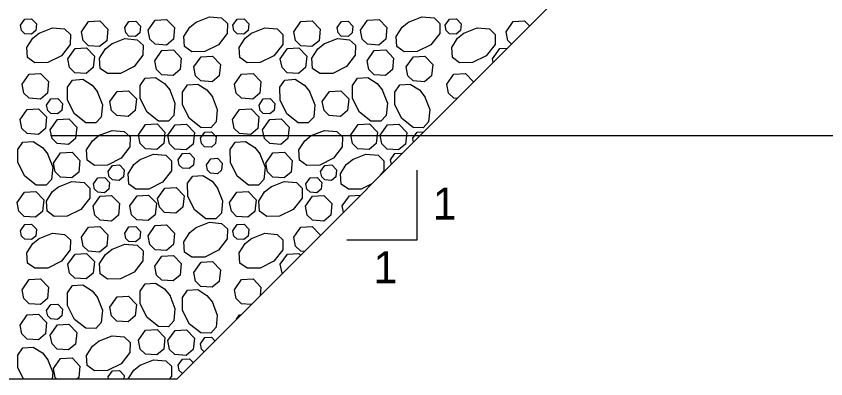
# Model space of a CAD drawing. Extents: x 638079 to 640019, y 297691 to 298879.
# Drawn here: x 639799.9 to 639876.1, y 298707.6 to 298741.7 of the extents above; entities that cross this region are included whole.
import ezdxf

# ---------------------------------------------------------------- set-up
doc = ezdxf.new("R2010")
doc.units = 0
doc.layers.add('1', color=7, linetype='Continuous')

msp = doc.modelspace()

# ---------------------------------------------------------------- linework, layer by layer
at = {"layer": '1'}
for p, q in [((639815.046, 298707.596), (639865.844, 298758.394)), ((639803.122, 298730.456), (639896.763, 298730.456)), ((639837.618, 298727.207), (639837.618, 298720.622)), ((639837.618, 298720.622), (639831.033, 298720.622)), ((639632.166, 298707.596), (639815.046, 298707.596))]:
    msp.add_line(p, q, dxfattribs=at)
for points in [[(639800.314, 298740.827), (639800.717, 298741.401), (639801.361, 298741.438), (639801.809, 298740.974), (639801.744, 298740.323), (639801.346, 298739.992), (639800.71, 298740.038), (639800.411, 298740.329), (639800.314, 298740.827)], [(639812.321, 298740.359), (639812.993, 298741.315), (639814.067, 298741.376), (639814.813, 298740.603), (639814.705, 298739.519), (639814.042, 298738.967), (639812.982, 298739.044), (639812.483, 298739.527), (639812.322, 298740.359)], [(639816.832, 298741.123), (639818.09, 298741.622), (639819.245, 298741.522), (639819.794, 298741), (639819.777, 298740.063), (639818.944, 298738.997), (639817.656, 298738.353), (639816.442, 298738.332), (639815.759, 298738.818), (639815.694, 298739.784), (639816.248, 298740.649), (639816.883, 298741.156)], [(639820.302, 298740.827), (639820.706, 298741.401), (639821.35, 298741.438), (639821.797, 298740.974), (639821.733, 298740.323), (639821.335, 298739.992), (639820.699, 298740.038), (639820.4, 298740.329), (639820.303, 298740.827)], [(639832.31, 298740.359), (639832.982, 298741.315), (639834.055, 298741.376), (639834.801, 298740.603), (639834.693, 298739.519), (639834.03, 298738.967), (639832.971, 298739.044), (639832.472, 298739.527), (639832.31, 298740.359)], [(639836.821, 298741.123), (639838.079, 298741.622), (639839.234, 298741.522), (639839.783, 298741), (639839.766, 298740.063), (639838.932, 298738.997), (639837.644, 298738.353), (639836.43, 298738.332), (639835.747, 298738.818), (639835.682, 298739.784), (639836.237, 298740.649), (639836.872, 298741.156)], [(639840.291, 298740.827), (639840.694, 298741.401), (639841.338, 298741.438), (639841.786, 298740.974), (639841.721, 298740.323), (639841.323, 298739.992), (639840.687, 298740.038), (639840.388, 298740.329), (639840.291, 298740.827)], [(639802.056, 298740.091), (639803.313, 298740.589), (639804.469, 298740.49), (639805.018, 298739.968), (639805, 298739.03), (639804.167, 298737.965), (639802.879, 298737.321), (639801.665, 298737.3), (639800.982, 298737.785), (639800.917, 298738.752), (639801.472, 298739.617), (639802.107, 298740.123)], [(639806.039, 298740.213), (639806.711, 298741.17), (639807.784, 298741.231), (639808.531, 298740.457), (639808.423, 298739.373), (639807.76, 298738.822), (639806.7, 298738.899), (639806.201, 298739.382), (639806.039, 298740.213)], [(639810.118, 298740.607), (639810.521, 298741.18), (639811.165, 298741.217), (639811.613, 298740.753), (639811.548, 298740.103), (639811.151, 298739.772), (639810.514, 298739.818), (639810.215, 298740.108), (639810.118, 298740.606)], [(639822.044, 298740.091), (639823.302, 298740.589), (639824.457, 298740.49), (639825.006, 298739.968), (639824.989, 298739.03), (639824.155, 298737.965), (639822.868, 298737.321), (639821.654, 298737.3), (639820.971, 298737.785), (639820.906, 298738.752), (639821.46, 298739.617), (639822.095, 298740.123)], [(639826.027, 298740.213), (639826.7, 298741.17), (639827.773, 298741.231), (639828.519, 298740.457), (639828.411, 298739.373), (639827.748, 298738.822), (639826.688, 298738.899), (639826.19, 298739.382), (639826.028, 298740.213)], [(639830.106, 298740.607), (639830.51, 298741.18), (639831.154, 298741.217), (639831.602, 298740.753), (639831.537, 298740.103), (639831.139, 298739.772), (639830.503, 298739.818), (639830.204, 298740.108), (639830.107, 298740.606)], [(639842.033, 298740.091), (639843.29, 298740.589), (639844.446, 298740.49), (639844.995, 298739.968), (639844.977, 298739.03), (639844.144, 298737.965), (639842.856, 298737.321), (639841.642, 298737.3), (639840.959, 298737.785), (639840.894, 298738.752), (639841.449, 298739.617), (639842.084, 298740.123)], [(639846.016, 298740.213), (639846.688, 298741.17), (639847.761, 298741.231), (639848.213, 298740.763)], [(639846.51, 298739.06), (639846.178, 298739.382), (639846.016, 298740.213)], [(639808.888, 298739.074), (639810.146, 298739.573), (639811.301, 298739.473), (639811.85, 298738.951), (639811.833, 298738.013), (639810.999, 298736.948), (639809.711, 298736.304), (639808.498, 298736.283), (639807.814, 298736.768), (639807.75, 298737.735), (639808.304, 298738.6), (639808.939, 298739.106)], [(639828.877, 298739.074), (639830.134, 298739.573), (639831.29, 298739.473), (639831.839, 298738.951), (639831.821, 298738.013), (639830.988, 298736.948), (639829.7, 298736.304), (639828.486, 298736.283), (639827.803, 298736.768), (639827.738, 298737.735), (639828.293, 298738.6), (639828.928, 298739.106)], [(639804.774, 298737.683), (639805.446, 298738.64), (639806.519, 298738.701), (639807.266, 298737.927), (639807.158, 298736.843), (639806.495, 298736.292), (639805.435, 298736.369), (639804.936, 298736.852), (639804.774, 298737.683)], [(639812.954, 298737.496), (639813.626, 298738.452), (639814.699, 298738.513), (639815.445, 298737.74), (639815.337, 298736.656), (639814.674, 298736.104), (639813.615, 298736.181), (639813.116, 298736.664), (639812.954, 298737.496)], [(639824.762, 298737.683), (639825.435, 298738.64), (639826.508, 298738.701), (639827.254, 298737.927), (639827.146, 298736.843), (639826.483, 298736.292), (639825.423, 298736.369), (639824.925, 298736.852), (639824.763, 298737.683)], [(639832.942, 298737.496), (639833.614, 298738.452), (639834.688, 298738.513), (639835.434, 298737.74), (639835.326, 298736.656), (639834.663, 298736.104), (639833.603, 298736.181), (639833.105, 298736.664), (639832.943, 298737.496)], [(639844.751, 298737.683), (639845.423, 298738.64), (639846.13, 298738.68)], [(639816.629, 298736.91), (639817.301, 298737.866), (639818.375, 298737.928), (639819.121, 298737.154), (639819.013, 298736.07), (639818.35, 298735.518), (639817.29, 298735.595), (639816.792, 298736.079), (639816.63, 298736.91)], [(639836.618, 298736.91), (639837.29, 298737.866), (639838.363, 298737.928), (639839.109, 298737.154), (639839.001, 298736.07), (639838.338, 298735.518), (639837.279, 298735.595), (639836.78, 298736.079), (639836.618, 298736.91)], [(639844.814, 298737.364), (639844.751, 298737.683)], [(639800.463, 298735.284), (639801.135, 298736.24), (639802.208, 298736.301), (639802.955, 298735.528), (639802.847, 298734.444), (639802.184, 298733.892), (639801.124, 298733.969), (639800.625, 298734.453), (639800.463, 298735.284)], [(639820.451, 298735.284), (639821.124, 298736.24), (639822.197, 298736.301), (639822.943, 298735.528), (639822.835, 298734.444), (639822.172, 298733.892), (639821.112, 298733.969), (639820.614, 298734.453), (639820.452, 298735.284)], [(639840.44, 298735.284), (639841.112, 298736.24), (639842.185, 298736.301), (639842.932, 298735.528), (639842.927, 298735.477)], [(639807.52, 298734.609), (639808.019, 298733.351), (639807.919, 298732.196), (639807.397, 298731.646), (639806.459, 298731.664), (639805.394, 298732.497), (639804.75, 298733.785), (639804.729, 298734.999), (639805.214, 298735.682), (639806.181, 298735.747), (639807.046, 298735.193), (639807.552, 298734.558)], [(639814.353, 298734.771), (639814.851, 298733.514), (639814.751, 298732.358), (639814.229, 298731.809), (639813.292, 298731.827), (639812.227, 298732.66), (639811.583, 298733.948), (639811.561, 298735.162), (639812.047, 298735.845), (639813.014, 298735.91), (639813.878, 298735.356), (639814.385, 298734.721)], [(639818.338, 298734.161), (639818.837, 298732.904), (639818.737, 298731.748), (639818.215, 298731.199), (639817.278, 298731.217), (639816.212, 298732.05), (639815.569, 298733.338), (639815.547, 298734.552), (639816.033, 298735.235), (639816.999, 298735.3), (639817.864, 298734.746), (639818.371, 298734.111)], [(639827.508, 298734.609), (639828.007, 298733.351), (639827.907, 298732.196), (639827.385, 298731.646), (639826.448, 298731.664), (639825.383, 298732.497), (639824.739, 298733.785), (639824.717, 298734.999), (639825.203, 298735.682), (639826.17, 298735.747), (639827.034, 298735.193), (639827.541, 298734.558)], [(639834.341, 298734.771), (639834.84, 298733.514), (639834.74, 298732.358), (639834.218, 298731.809), (639833.28, 298731.827), (639832.215, 298732.66), (639831.571, 298733.948), (639831.55, 298735.162), (639832.035, 298735.845), (639833.002, 298735.91), (639833.867, 298735.356), (639834.373, 298734.721)], [(639838.327, 298734.161), (639838.825, 298732.904), (639838.726, 298731.748), (639838.204, 298731.199), (639837.266, 298731.217), (639836.201, 298732.05), (639835.557, 298733.338), (639835.536, 298734.552), (639836.021, 298735.235), (639836.988, 298735.3), (639837.853, 298734.746), (639838.359, 298734.111)], [(639841.397, 298733.947), (639841.101, 298733.969), (639840.602, 298734.453), (639840.44, 298735.284)], [(639808.728, 298733.657), (639809.4, 298734.614), (639810.473, 298734.675), (639811.22, 298733.901), (639811.112, 298732.817), (639810.449, 298732.266), (639809.389, 298732.342), (639808.89, 298732.826), (639808.728, 298733.657)], [(639828.716, 298733.657), (639829.388, 298734.614), (639830.462, 298734.675), (639831.208, 298733.901), (639831.1, 298732.817), (639830.437, 298732.266), (639829.377, 298732.342), (639828.879, 298732.826), (639828.717, 298733.657)], [(639802.773, 298733.324), (639803.176, 298733.898), (639803.82, 298733.935), (639804.268, 298733.471), (639804.203, 298732.82), (639803.805, 298732.489), (639803.169, 298732.536), (639802.87, 298732.826), (639802.773, 298733.324)], [(639822.761, 298733.324), (639823.165, 298733.898), (639823.809, 298733.935), (639824.256, 298733.471), (639824.192, 298732.82), (639823.794, 298732.489), (639823.158, 298732.536), (639822.859, 298732.826), (639822.762, 298733.324)], [(639800.275, 298731.963), (639800.947, 298732.919), (639802.02, 298732.981), (639802.766, 298732.207), (639802.658, 298731.123), (639801.995, 298730.571), (639800.935, 298730.648), (639800.437, 298731.132), (639800.275, 298731.963)], [(639820.263, 298731.963), (639820.935, 298732.919), (639822.009, 298732.981), (639822.755, 298732.207), (639822.647, 298731.123), (639821.984, 298730.571), (639820.924, 298730.648), (639820.425, 298731.132), (639820.264, 298731.963)], [(639803.115, 298731.014), (639803.788, 298731.97), (639804.861, 298732.031), (639805.607, 298731.258), (639805.499, 298730.173), (639804.836, 298729.622), (639803.776, 298729.699), (639803.278, 298730.182), (639803.116, 298731.013)], [(639811.418, 298730.54), (639812.09, 298731.496), (639813.164, 298731.557), (639813.91, 298730.784), (639813.802, 298729.7), (639813.139, 298729.148), (639812.079, 298729.225), (639811.581, 298729.708), (639811.419, 298730.539)], [(639814.184, 298730.499), (639814.856, 298731.455), (639815.929, 298731.517), (639816.676, 298730.743), (639816.568, 298729.659), (639815.904, 298729.107), (639814.845, 298729.184), (639814.346, 298729.668), (639814.184, 298730.499)], [(639823.104, 298731.014), (639823.776, 298731.97), (639824.849, 298732.031), (639825.596, 298731.258), (639825.488, 298730.173), (639824.825, 298729.622), (639823.765, 298729.699), (639823.266, 298730.182), (639823.104, 298731.013)], [(639831.407, 298730.54), (639832.079, 298731.496), (639833.152, 298731.557), (639833.898, 298730.784), (639833.79, 298729.7), (639833.127, 298729.148), (639832.068, 298729.225), (639831.569, 298729.708), (639831.407, 298730.539)], [(639834.172, 298730.499), (639834.844, 298731.455), (639835.918, 298731.517), (639836.664, 298730.743), (639836.556, 298729.659), (639835.893, 298729.107), (639834.833, 298729.184), (639834.335, 298729.668), (639834.173, 298730.499)], [(639807.668, 298730.452), (639808.926, 298730.951), (639810.081, 298730.851), (639810.63, 298730.329), (639810.613, 298729.391), (639809.779, 298728.326), (639808.491, 298727.682), (639807.278, 298727.661), (639806.594, 298728.146), (639806.53, 298729.113), (639807.084, 298729.978), (639807.719, 298730.484)], [(639817.243, 298730.204), (639817.646, 298730.777), (639818.29, 298730.814), (639818.738, 298730.35), (639818.673, 298729.7), (639818.275, 298729.369), (639817.639, 298729.415), (639817.34, 298729.705), (639817.243, 298730.203)], [(639827.657, 298730.452), (639828.914, 298730.951), (639830.07, 298730.851), (639830.619, 298730.329), (639830.601, 298729.391), (639829.768, 298728.326), (639828.48, 298727.682), (639827.266, 298727.661), (639826.583, 298728.146), (639826.518, 298729.113), (639827.073, 298729.978), (639827.707, 298730.484)], [(639837.231, 298730.204), (639837.634, 298730.777), (639838.263, 298730.813)], [(639837.3, 298729.85), (639837.231, 298730.203)], [(639802.843, 298728.752), (639803.342, 298727.495), (639803.242, 298726.339), (639802.72, 298725.79), (639801.782, 298725.808), (639800.717, 298726.641), (639800.073, 298727.929), (639800.052, 298729.143), (639800.537, 298729.826), (639801.504, 298729.891), (639802.369, 298729.336), (639802.875, 298728.701)], [(639822.831, 298728.752), (639823.33, 298727.495), (639823.23, 298726.339), (639822.708, 298725.79), (639821.771, 298725.808), (639820.705, 298726.641), (639820.062, 298727.929), (639820.04, 298729.143), (639820.526, 298729.826), (639821.493, 298729.891), (639822.357, 298729.336), (639822.864, 298728.701)], [(639803.414, 298727.867), (639804.087, 298728.824), (639805.16, 298728.885), (639805.906, 298728.111), (639805.798, 298727.027), (639805.135, 298726.476), (639804.075, 298726.552), (639803.577, 298727.036), (639803.415, 298727.867)], [(639811.57, 298728.206), (639812.828, 298728.704), (639813.983, 298728.604), (639814.532, 298728.082), (639814.515, 298727.145), (639813.681, 298726.079), (639812.393, 298725.436), (639811.18, 298725.414), (639810.496, 298725.9), (639810.432, 298726.867), (639810.986, 298727.731), (639811.621, 298728.238)], [(639815.162, 298728.186), (639815.565, 298728.76), (639816.209, 298728.797), (639816.657, 298728.332), (639816.592, 298727.682), (639816.194, 298727.351), (639815.558, 298727.397), (639815.259, 298727.687), (639815.162, 298728.186)], [(639823.403, 298727.867), (639824.075, 298728.824), (639825.149, 298728.885), (639825.895, 298728.111), (639825.787, 298727.027), (639825.124, 298726.476), (639824.064, 298726.552), (639823.565, 298727.036), (639823.403, 298727.867)], [(639831.558, 298728.206), (639832.816, 298728.704), (639833.971, 298728.604), (639834.521, 298728.082), (639834.503, 298727.145), (639834.176, 298726.727)], [(639835.15, 298728.186), (639835.554, 298728.76), (639836.198, 298728.797), (639836.222, 298728.772)], [(639808.573, 298727.083), (639808.977, 298727.657), (639809.621, 298727.693), (639810.068, 298727.229), (639810.004, 298726.579), (639809.606, 298726.248), (639808.97, 298726.294), (639808.671, 298726.584), (639808.574, 298727.083)], [(639817.81, 298727.713), (639818.213, 298728.287), (639818.857, 298728.324), (639819.305, 298727.859), (639819.24, 298727.209), (639818.843, 298726.878), (639818.207, 298726.924), (639817.907, 298727.214), (639817.81, 298727.713)], [(639828.562, 298727.083), (639828.965, 298727.657), (639829.609, 298727.693), (639830.057, 298727.229), (639829.992, 298726.579), (639829.594, 298726.248), (639828.958, 298726.294), (639828.659, 298726.584), (639828.562, 298727.083)], [(639833.388, 298725.938), (639832.382, 298725.436), (639831.168, 298725.414), (639830.485, 298725.9), (639830.42, 298726.867), (639830.974, 298727.731), (639831.609, 298728.238)], [(639835.23, 298727.78), (639835.151, 298728.186)], [(639803.884, 298725.644), (639805.142, 298726.142), (639806.297, 298726.042), (639806.846, 298725.52), (639806.829, 298724.583), (639805.995, 298723.518), (639804.708, 298722.874), (639803.494, 298722.852), (639802.811, 298723.338), (639802.746, 298724.305), (639803.3, 298725.169), (639803.935, 298725.676)], [(639807.186, 298725.916), (639807.59, 298726.49), (639808.234, 298726.527), (639808.681, 298726.063), (639808.617, 298725.412), (639808.219, 298725.081), (639807.583, 298725.127), (639807.284, 298725.417), (639807.187, 298725.916)], [(639818.826, 298725.58), (639819.325, 298724.322), (639819.225, 298723.167), (639818.703, 298722.618), (639817.765, 298722.635), (639816.7, 298723.469), (639816.056, 298724.757), (639816.035, 298725.97), (639816.52, 298726.654), (639817.487, 298726.718), (639818.352, 298726.164), (639818.858, 298725.529)], [(639823.873, 298725.644), (639825.131, 298726.142), (639826.286, 298726.042), (639826.835, 298725.52), (639826.817, 298724.583), (639825.984, 298723.518), (639824.696, 298722.874), (639823.482, 298722.852), (639822.799, 298723.338), (639822.734, 298724.305), (639823.289, 298725.169), (639823.924, 298725.676)], [(639827.175, 298725.916), (639827.578, 298726.49), (639828.222, 298726.527), (639828.67, 298726.063), (639828.605, 298725.412), (639828.207, 298725.081), (639827.571, 298725.127), (639827.272, 298725.417), (639827.175, 298725.916)], [(639813.217, 298724.555), (639813.889, 298725.512), (639814.963, 298725.573), (639815.709, 298724.799), (639815.601, 298723.715), (639814.938, 298723.164), (639813.878, 298723.241), (639813.38, 298723.724), (639813.218, 298724.555)], [(639800.007, 298724.169), (639800.68, 298725.126), (639801.753, 298725.187), (639802.499, 298724.413), (639802.391, 298723.329), (639801.728, 298722.778), (639800.668, 298722.854), (639800.17, 298723.338), (639800.008, 298724.169)], [(639807.141, 298723.815), (639807.814, 298724.771), (639808.887, 298724.832), (639809.633, 298724.059), (639809.525, 298722.974), (639808.862, 298722.423), (639807.802, 298722.5), (639807.304, 298722.983), (639807.142, 298723.814)], [(639810.61, 298723.854), (639811.282, 298724.81), (639812.356, 298724.872), (639813.102, 298724.098), (639812.994, 298723.014), (639812.331, 298722.462), (639811.271, 298722.539), (639810.772, 298723.023), (639810.611, 298723.854)], [(639819.996, 298724.169), (639820.668, 298725.126), (639821.742, 298725.187), (639822.488, 298724.413), (639822.38, 298723.329), (639821.717, 298722.778), (639820.657, 298722.854), (639820.158, 298723.338), (639819.997, 298724.169)], [(639827.13, 298723.815), (639827.802, 298724.771), (639828.876, 298724.832), (639829.622, 298724.059), (639829.514, 298722.974), (639828.851, 298722.423), (639827.791, 298722.5), (639827.292, 298722.983), (639827.131, 298723.814)], [(639830.598, 298723.854), (639831.271, 298724.81), (639832.32, 298724.87)], [(639830.714, 298723.264), (639830.599, 298723.854)], [(639816.832, 298721.809), (639818.09, 298722.307), (639819.245, 298722.208), (639819.794, 298721.686), (639819.777, 298720.748), (639818.944, 298719.683), (639817.656, 298719.039), (639816.442, 298719.018), (639815.759, 298719.503), (639815.694, 298720.47), (639816.248, 298721.335), (639816.883, 298721.841)], [(639800.314, 298721.513), (639800.717, 298722.087), (639801.361, 298722.123), (639801.809, 298721.659), (639801.744, 298721.009), (639801.346, 298720.678), (639800.71, 298720.724), (639800.411, 298721.014), (639800.314, 298721.513)], [(639806.039, 298720.899), (639806.711, 298721.855), (639807.784, 298721.917), (639808.531, 298721.143), (639808.423, 298720.059), (639807.76, 298719.507), (639806.7, 298719.584), (639806.201, 298720.068), (639806.039, 298720.899)], [(639810.118, 298721.292), (639810.521, 298721.866), (639811.165, 298721.903), (639811.613, 298721.438), (639811.548, 298720.788), (639811.151, 298720.457), (639810.514, 298720.503), (639810.215, 298720.793), (639810.118, 298721.292)], [(639812.321, 298721.044), (639812.993, 298722.001), (639814.067, 298722.062), (639814.813, 298721.288), (639814.705, 298720.204), (639814.042, 298719.653), (639812.982, 298719.729), (639812.483, 298720.213), (639812.322, 298721.044)], [(639820.302, 298721.513), (639820.706, 298722.087), (639821.35, 298722.123), (639821.797, 298721.659), (639821.733, 298721.009), (639821.335, 298720.678), (639820.699, 298720.724), (639820.4, 298721.014), (639820.303, 298721.513)], [(639826.027, 298720.899), (639826.7, 298721.855), (639827.773, 298721.917), (639828.519, 298721.143), (639828.511, 298721.061)], [(639802.056, 298720.776), (639803.313, 298721.275), (639804.469, 298721.175), (639805.018, 298720.653), (639805, 298719.716), (639804.167, 298718.65), (639802.879, 298718.006), (639801.665, 298717.985), (639800.982, 298718.471), (639800.917, 298719.437), (639801.472, 298720.302), (639802.107, 298720.809)], [(639822.044, 298720.776), (639823.302, 298721.275), (639824.457, 298721.175), (639825.006, 298720.653), (639824.989, 298719.716), (639824.155, 298718.65), (639822.868, 298718.006), (639821.654, 298717.985), (639820.971, 298718.471), (639820.906, 298719.437), (639821.46, 298720.302), (639822.095, 298720.809)], [(639827.01, 298719.561), (639826.688, 298719.584), (639826.19, 298720.068), (639826.028, 298720.899)], [(639808.888, 298719.76), (639810.146, 298720.258), (639811.301, 298720.158), (639811.85, 298719.636), (639811.833, 298718.699), (639810.999, 298717.634), (639809.711, 298716.99), (639808.498, 298716.968), (639807.814, 298717.454), (639807.75, 298718.421), (639808.304, 298719.285), (639808.939, 298719.792)], [(639804.774, 298718.369), (639805.446, 298719.325), (639806.519, 298719.387), (639807.266, 298718.613), (639807.158, 298717.529), (639806.495, 298716.977), (639805.435, 298717.054), (639804.936, 298717.538), (639804.774, 298718.369)], [(639824.762, 298718.369), (639825.435, 298719.325), (639826.508, 298719.387), (639826.669, 298719.219)], [(639812.954, 298718.181), (639813.626, 298719.138), (639814.699, 298719.199), (639815.445, 298718.425), (639815.337, 298717.341), (639814.674, 298716.79), (639813.615, 298716.866), (639813.116, 298717.35), (639812.954, 298718.181)], [(639816.629, 298717.596), (639817.301, 298718.552), (639818.375, 298718.613), (639819.121, 298717.84), (639819.013, 298716.756), (639818.35, 298716.204), (639817.29, 298716.281), (639816.792, 298716.764), (639816.63, 298717.595)], [(639824.957, 298717.507), (639824.925, 298717.538), (639824.763, 298718.369)], [(639800.463, 298715.969), (639801.135, 298716.926), (639802.208, 298716.987), (639802.955, 298716.213), (639802.847, 298715.129), (639802.184, 298714.578), (639801.124, 298714.654), (639800.625, 298715.138), (639800.463, 298715.969)], [(639820.451, 298715.969), (639821.124, 298716.926), (639822.197, 298716.987), (639822.943, 298716.213), (639822.864, 298715.414)], [(639807.52, 298715.294), (639808.019, 298714.037), (639807.919, 298712.881), (639807.397, 298712.332), (639806.459, 298712.35), (639805.394, 298713.183), (639804.75, 298714.471), (639804.729, 298715.685), (639805.214, 298716.368), (639806.181, 298716.432), (639807.046, 298715.878), (639807.552, 298715.243)], [(639814.353, 298715.457), (639814.851, 298714.199), (639814.751, 298713.044), (639814.229, 298712.495), (639813.292, 298712.512), (639812.227, 298713.346), (639811.583, 298714.634), (639811.561, 298715.847), (639812.047, 298716.531), (639813.014, 298716.595), (639813.878, 298716.041), (639814.385, 298715.406)], [(639818.338, 298714.847), (639818.837, 298713.589), (639818.737, 298712.434), (639818.215, 298711.885), (639817.278, 298711.902), (639816.212, 298712.736), (639815.569, 298714.024), (639815.547, 298715.237), (639816.033, 298715.921), (639816.999, 298715.985), (639817.864, 298715.431), (639818.371, 298714.796)], [(639822.037, 298714.587), (639821.112, 298714.654), (639820.614, 298715.138), (639820.452, 298715.969)], [(639808.728, 298714.343), (639809.4, 298715.299), (639810.473, 298715.36), (639811.22, 298714.587), (639811.112, 298713.503), (639810.449, 298712.951), (639809.389, 298713.028), (639808.89, 298713.511), (639808.728, 298714.343)], [(639802.773, 298714.01), (639803.176, 298714.584), (639803.82, 298714.621), (639804.268, 298714.156), (639804.203, 298713.506), (639803.805, 298713.175), (639803.169, 298713.221), (639802.87, 298713.511), (639802.773, 298714.01)], [(639800.275, 298712.649), (639800.947, 298713.605), (639802.02, 298713.666), (639802.766, 298712.893), (639802.658, 298711.808), (639801.995, 298711.257), (639800.935, 298711.334), (639800.437, 298711.817), (639800.275, 298712.648)], [(639820.654, 298713.204), (639820.935, 298713.605), (639821.062, 298713.612)], [(639803.115, 298711.699), (639803.788, 298712.655), (639804.861, 298712.717), (639805.607, 298711.943), (639805.499, 298710.859), (639804.836, 298710.307), (639803.776, 298710.384), (639803.278, 298710.868), (639803.116, 298711.699)], [(639807.668, 298711.138), (639808.926, 298711.636), (639810.081, 298711.536), (639810.63, 298711.014), (639810.613, 298710.077), (639809.779, 298709.012), (639808.491, 298708.368), (639807.278, 298708.346), (639806.594, 298708.832), (639806.53, 298709.799), (639807.084, 298710.663), (639807.719, 298711.17)], [(639811.418, 298711.225), (639812.09, 298712.182), (639813.164, 298712.243), (639813.91, 298711.469), (639813.802, 298710.385), (639813.139, 298709.834), (639812.079, 298709.91), (639811.581, 298710.394), (639811.419, 298711.225)], [(639814.184, 298711.184), (639814.856, 298712.141), (639815.929, 298712.202), (639816.676, 298711.428), (639816.568, 298710.344), (639815.904, 298709.793), (639814.845, 298709.87), (639814.346, 298710.353), (639814.184, 298711.184)], [(639817.243, 298710.889), (639817.646, 298711.463), (639818.29, 298711.5), (639818.614, 298711.164)], [(639817.594, 298710.144), (639817.34, 298710.39), (639817.243, 298710.889)], [(639800.582, 298707.596), (639800.073, 298708.614), (639800.052, 298709.828), (639800.537, 298710.511), (639801.504, 298710.576), (639802.369, 298710.022), (639802.875, 298709.387)], [(639802.843, 298709.438), (639803.342, 298708.18), (639803.291, 298707.596)], [(639803.414, 298708.553), (639804.087, 298709.509), (639805.16, 298709.57), (639805.906, 298708.797), (639805.798, 298707.713), (639805.658, 298707.596)], [(639811.57, 298708.891), (639812.828, 298709.39), (639813.983, 298709.29), (639814.532, 298708.768), (639814.515, 298707.83), (639814.332, 298707.596)], [(639815.162, 298708.871), (639815.565, 298709.445), (639816.209, 298709.482), (639816.564, 298709.114)], [(639810.46, 298707.596), (639810.986, 298708.417), (639811.621, 298708.923)], [(639815.545, 298708.095), (639815.259, 298708.373), (639815.162, 298708.871)], [(639803.706, 298707.596), (639803.577, 298707.721), (639803.415, 298708.553)], [(639808.573, 298707.768), (639808.977, 298708.342), (639809.621, 298708.379), (639810.068, 298707.915), (639810.037, 298707.596)], [(639808.607, 298707.596), (639808.574, 298707.768)]]:
    msp.add_lwpolyline(points, dxfattribs=at)

# ---------------------------------------------------------------- texts
for p in [(639839.119, 298722.565), (639833.541, 298716.583)]:
    msp.add_text('1', height=3, dxfattribs=at).set_placement(p)

doc.saveas('drawing.dxf')
